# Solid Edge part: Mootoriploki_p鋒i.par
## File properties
Author: KULL
Template: Iso Metric Part.par
Last saved by: KULL
Revision: 7
Application: Solid Edge
Accuracy: 0,990
Face Style: Model Default
Fill Style: Normal
Coef. of Thermal Exp: 0.0
Thermal Conductivity: 0.0
Specific Heat: 0.0
Modulus of Elasticity: 0.0
Poisson's Ratio: 0.0
Yield Stress: 0.0
Ultimate Stress: 0.0
Elongation: 0.0
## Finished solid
Body 1: solid body, 64 faces, 166 edges, 104 vertices.
  Faces by surface: plane 48, cylinder 10, torus 6
  Edges by curve: line 128, circle 38
Bounding box of the edges (mm; curved faces can reach further): 102.794 x 41.246 x 20.427, from (-51.3987, -20.6232, -4.4677) to (51.3957, 20.6232, 15.959).
Cylindrical faces by radius (mm): R3 x2, R4 x4, R8 x2, R9.5 x2
Toroidal faces (ring radius, tube radius in mm): R8.2 r0.2 x2, R9.3 r0.2 x2, R11.5 r2 x2
Planar faces by outward normal: +x 8, +z 17, -x 8, -z 1, oblique 14
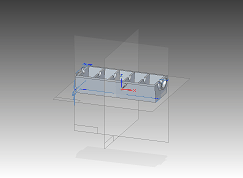
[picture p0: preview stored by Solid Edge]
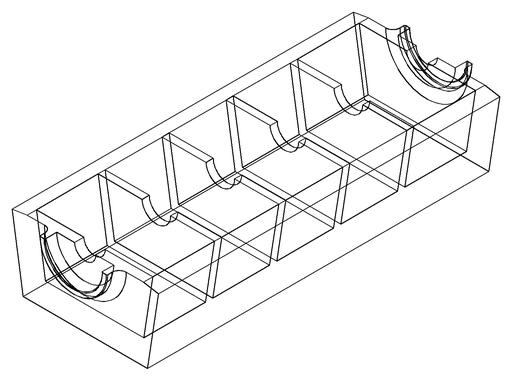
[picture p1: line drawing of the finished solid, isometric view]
